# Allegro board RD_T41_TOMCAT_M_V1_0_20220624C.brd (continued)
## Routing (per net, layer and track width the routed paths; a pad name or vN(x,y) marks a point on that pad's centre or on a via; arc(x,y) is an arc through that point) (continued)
GMAC_TXD0: length 11.3
  TOP w0.102: U6.R11 27.47,22.53 27.02,22.53 26.82,22.33 20.21,22.33 19.35,21.46 19.35,19.81 19.22,19.68 U8.16
GMAC_TXD1: length 10.2
  TOP w0.102: U8.17 18.08,20.57 20.09,22.58 26.23,22.58 26.29,22.53 26.62,22.53 26.94,22.86 U6.T11
GMAC_TXEN: length 11.2
  TOP w0.102: U8.20 16.58,20.9 16.84,21.16 18.31,21.16 19.96,22.81 26.45,22.81 U6.U11
HPOUTL: length 7.6
  TOP w0.254: C107.2 20.61,30.25 26.25,30.25 U6.T1
I2C0_SCK: length 15.3
  TOP w0.102: U6.J4 32.03,27.74 32.03,34.42 v1(31.11,35.33)
  BOTTOM w0.102: v1(31.11,35.33) 30.81,35.03 25.73,35.03 25.25,34.55 J3.20
I2C0_SDA: length 13.4
  TOP w0.102: U6.J1 31.7,29.79 31.8,29.9 31.8,34.06 30.5,35.36 v1(30.5,35.48)
  BOTTOM w0.102: v1(30.5,35.48) 30.32,35.31 25.4,35.31 24.75,35.95 J3.19
IR: length 28.3
  TOP w0.102: v1(37.49,22.1) 37.11,22.1 37,22.21 U6.B12
  L3_PWR w0.102: v1(40.69,31.72) 40.56,31.85 34.16,31.85 v1(33.85,32.16)
  BOTTOM w0.102: J3.26 28.25,33.62 29.82,32.05 33.75,32.05 v1(33.85,32.16) ; v1(40.69,31.72) 40.84,31.72 41.4,31.17 41.4,23.01 40.41,22.02 37.56,22.02 v1(37.49,22.1)
IRCUTN: length 37.1
  TOP w0.102: U6.E17 35.06,18.19 37.13,18.19 38.55,19.61 v1(38.55,20.98)
  BOTTOM w0.102: J3.25 27.75,35.85 27.94,35.66 30.02,35.66 31.21,36.86 36.45,36.86 41.93,31.37 41.93,22.58 40.76,21.41 38.99,21.41 v1(38.55,20.98)
IRCUTP: length 36.6
  TOP w0.102: U6.E16 34.3,19.42 35.25,18.47 37.08,18.47 38.02,19.41 v1(38.02,21.54)
  BOTTOM w0.102: J3.24 27.25,34.59 27.45,34.8 30.53,34.8 31.37,33.96 35.23,33.96 35.81,34.54 38.43,34.54 41.65,31.32 41.65,22.76 40.59,21.69 38.17,21.69 v1(38.02,21.54)
LINKA: length 3.2
  TOP w0.102: R75.2 11.58,22.06 11.24,21.72 R76.1 10.47,20.47 J5.8
MCLK: length 1.1
  TOP w0.102: R67.2 34.3,29.8 U6.E1
MDI_RN: length 1.9
  TOP w0.104: R40.2 20.01,12.19 U9.1
MDI_RP: length 1.6
  TOP w0.104: U9.3 R39.2
MDI_TN: length 4.4
  TOP w0.104: U9.6 13.66,11.4 13.36,11.71 12.87,11.71 12.67,11.91 12.67,12.12 13.67,13.12 R36.2
MDI_TP: length 3.6
  TOP w0.104: R13.2 12.91,12.74 12.39,12.22 12.39,11.89 12.19,11.68 11.5,11.68 11.12,11.3 U9.8
MICBIAS: length 11.7
  TOP w0.254: U6.P3 v1(28.12,28.38) ; R81.1 20.61,33.07 C110.1 v1(21.54,32.78)
  BOTTOM w0.254: v1(28.12,28.38) 28.12,28.84 28.01,28.95 28.01,30.54 27.43,31.13 C79.1 C78.1 26.44,31.13 25.28,32.28 22.03,32.28 v1(21.54,32.78)
MICNL: length 12.1
  TOP w0.152: C68.2 23.4,31.62 20.62,31.62 20.23,32.02 17.7,32.02 R48.1 16.81,31.84 C105.1 16.3,32.02 14.08,32.02 13.29,32.81 J6.1
MICPL: length 10.7
  TOP w0.152: C67.2 23.43,31.98 20.77,31.98 20.37,32.37 17.7,32.37 R51.2 16.81,32.55 C105.2 16.3,32.37 14.93,32.37 14.54,32.76 J6.2
MIPI_RX_CLKN: length 23.9
  TOP w0.104: v1(15.62,34.99) 15.81,34.99 16.4,34.39 19.4,34.39 21.12,36.11 23.31,36.11 24.79,34.63 27.66,34.63 28,34.29 28,34.14 27.83,33.96 27.83,33.82 27.93,33.71 28.08,33.71 28.26,33.89 28.4,33.89 28.51,33.78 28.51,33.63 28.33,33.46 28.33,33.31 28.44,33.2 28.59,33.2 28.76,33.38 28.91,33.38 29.02,33.28 29.02,33.13 28.84,32.95 28.84,32.8 28.94,32.7 29.09,32.7 29.27,32.87 29.42,32.87 29.74,32.55 29.74,28.71 U6.M2
  BOTTOM w0.104: J3.2 16.25,34.55 15.81,34.99 v1(15.62,34.99)
MIPI_RX_CLKP: length 23.9
  TOP w0.104: v1(15.99,35.37) 15.99,35.17 16.51,34.65 19.29,34.65 21.02,36.37 23.41,36.37 24.9,34.89 27.77,34.89 30,32.66 30,29.74 29.95,29.69 29.95,29.16 30.07,29.03 30.07,28.38 U6.L3
  BOTTOM w0.104: J3.3 16.75,35.27 16.49,35.01 16.15,35.01 15.99,35.17 v1(15.99,35.37)
MIPI_RX_DN0: length 23.7
  TOP w0.102: 30.75,29.74 30.75,29.6 30.76,29.59 30.76,29.07 U6.L2
  TOP w0.104: 30.75,29.74 30.75,29.93 31.03,30.22 31.03,33.84 29.53,35.35 29.17,35.35 28.92,35.1 28.77,35.1 28.67,35.21 28.67,35.36 29.33,36.02 29.33,36.59 28.71,37.21 20.43,37.21 18.93,35.71 v1(18.73,35.71)
  BOTTOM w0.104: J3.5 17.75,35.97 18.31,35.41 18.62,35.41 18.73,35.52 v1(18.73,35.71)
MIPI_RX_DN1: length 23.8
  TOP w0.104: U6.N1 29.23,29.49 29.23,31.03 28.9,31.35 28.76,31.35 28.62,31.22 28.47,31.22 28.36,31.32 28.36,31.47 28.5,31.61 28.5,31.75 28.4,31.86 28.25,31.86 28.11,31.72 27.96,31.72 27.86,31.83 27.86,31.98 28,32.11 28,32.26 26.88,33.38 26.88,33.8 26.78,33.9 26.63,33.9 26.52,33.8 26.52,33.02 26.26,32.76 25.9,32.76 25.65,33.02 25.65,33.8 25.54,33.9 25.39,33.9 25.29,33.8 25.29,33.29 25.02,33.01 23.76,33.01 23.51,33.27 23.51,33.63 24.01,34.13 24.01,34.31 23.82,34.5 23.64,34.5 22.48,33.33 22.12,33.33 21.76,33.68 21.76,34.05 22.71,35 22.71,35.16 22.53,35.34 22.39,35.34 21.81,34.77 21.45,34.77 21.21,35.01 v1(21.02,35.01)
  BOTTOM w0.104: J3.8 19.25,34.6 19.99,35.33 20.89,35.33 21.02,35.2 v1(21.02,35.01)
MIPI_RX_DP0: length 23.7
  TOP w0.102: 30.4,29.74 U6.L1
  TOP w0.104: v1(19.11,35.34) 19.11,35.52 20.54,36.95 28.6,36.95 29.07,36.49 29.07,36.12 28.41,35.46 28.41,35.1 28.67,34.84 29.03,34.84 29.27,35.09 29.42,35.09 29.65,34.86 29.65,34.71 29.47,34.54 29.47,34.39 29.58,34.28 29.73,34.28 29.9,34.46 30.05,34.46 30.16,34.36 30.16,34.21 29.98,34.03 29.98,33.88 30.09,33.78 30.23,33.78 30.41,33.95 30.56,33.95 30.78,33.74 30.78,30.32 30.4,29.94 30.4,29.74
  BOTTOM w0.104: J3.6 18.25,35.04 18.35,35.15 18.72,35.15 18.91,35.34 v1(19.11,35.34)
MIPI_RX_DP1: length 23.8
  TOP w0.104: v1(21.39,35.39) 21.39,35.19 21.56,35.03 21.71,35.03 22.28,35.6 22.64,35.6 22.97,35.27 22.97,34.89 22.02,33.94 22.02,33.79 22.22,33.59 22.37,33.59 23.54,34.75 23.93,34.75 24.27,34.42 24.27,34.03 23.77,33.53 23.77,33.38 23.87,33.27 24.91,33.27 25.03,33.39 25.03,33.91 25.28,34.16 25.65,34.16 25.91,33.91 25.91,33.12 26.01,33.02 26.16,33.02 26.26,33.13 26.26,33.91 26.52,34.16 26.88,34.16 27.14,33.91 27.14,33.48 29.49,31.14 29.49,29.29 29.42,29.22 29.42,28.38 U6.M3
  BOTTOM w0.104: v1(21.39,35.39) 21.2,35.39 20.99,35.6 20.1,35.6 19.75,35.95 J3.9
MSC0_CLK_PB04: length 6.4
  TOP w0.102: J2.5 28.22,15.14 28.52,15.44 31.47,15.44 32.46,16.43 R25.1
MSC0_CMD_PB05: length 8.3
  TOP w0.102: v1(30.42,12.85) J2.3 30.42,15.08 30.55,15.21 31.67,15.21 33,16.54 U6.G17
  BOTTOM w0.102: v1(30.42,12.85) 30.43,12.86 R30.2
MSC0_D0_PB00: length 12.8
  TOP w0.102: v1(26.02,12.85) J2.7 26.02,15.08 26.72,15.77 31.36,15.77 31.92,16.34 31.92,18.36 32.33,18.77 32.33,19.59 U6.H16
  BOTTOM w0.102: R29.2 26.1,12.93 v1(26.02,12.85)
MSC0_D1_PB01: length 14
  TOP w0.102: v1(24.92,12.85) J2.8 24.92,14.61 26.36,16.05 31.31,16.05 31.7,16.43 31.7,18.47 32.03,18.8 32.03,19.93 U6.J15
  BOTTOM w0.102: R31.2 24.85,12.92 v1(24.92,12.85)
MSC0_D2_PB02: length 8.5
  TOP w0.102: v1(32.62,12.85) J2.1 32.62,15.4 33.52,16.31 33.52,19.28 33.32,19.48 33.32,19.93 U6.G15
  BOTTOM w0.102: v1(32.62,12.85) 32.61,12.86 R32.2
MSC0_D3_PB03: length 8.1
  TOP w0.102: U6.G16 33,19.48 33.32,19.15 33.32,18.75 33.27,18.69 33.27,16.4 31.52,14.65 J2.2 v1(31.52,12.86)
  BOTTOM w0.102: v1(31.52,12.86) 31.52,12.86 R33.2
PHY_LED0: length 22.2
  TOP w0.102: R74.1 12.8,19.98 12.8,20.37 13.15,20.73 13.15,23.24 13.79,23.88 15.02,23.88 15.15,24 22.46,24 23.55,25.1 25.12,25.1 v1(25.78,24.43) ; U6.R13 v1(27.48,21.24)
  L3_PWR w0.102: v1(25.78,24.43) 27.48,22.73 v1(27.48,21.24)
PHY_LED1: length 19.6
  TOP w0.102: R75.1 12.84,24.31 v1(13.74,24.31) ; U6.R15 v1(27.48,19.94)
  L3_PWR w0.102: v1(27.48,19.94) 27.05,19.94 26.26,20.73 26.26,21.41 22.7,24.97 17.47,24.97 16.81,24.31 v1(13.74,24.31)
PHY_RST_N: length 3.9
  TOP w0.102: U6.T13 26.8,21.21 26.31,21.21 26.13,21.39 24.6,21.39 C61.2 R99.1
PHYLED0: length 8.4
  TOP w0.102: v1(14.52,23.24) 14.37,23.09 14.37,22.04 R88.2 14.58,21.38 U8.24 ; R77.2 12.9,20.97 12.9,23.04 v1(12.75,23.19)
  BOTTOM w0.102: v1(14.52,23.24) 14.19,23.57 13.64,23.57 13.25,23.19 v1(12.75,23.19)
PHYLED1: length 5.2
  TOP w0.102: R89.2 v1(13.92,21.18) 13.92,20.78 13.31,20.17 13.31,19.81 13.44,19.68 U8.25 ; R76.2 12.28,21.75 v1(12.49,21.97)
  BOTTOM w0.102: v1(12.49,21.97) 13.13,21.97 v1(13.92,21.18)
PLL_AVDD: length 2.9
  TOP w0.254: U6.D3 v1(35.27,28.38)
  BOTTOM w0.254: v1(35.27,28.38) 35.27,28.98 C63.1 C30.1 35.26,30.73 FB3.1
POR_CTRL: length 2.7
  TOP w0.102: R20.2 R78.2 30.81,18.45 30.81,19.37 U6.K16
PPRST_: length 20
  TOP w0.102: v1(36.01,12.88) 36.01,14.12 36.62,14.73 37.6,14.73 R62.2 C111.1 40.19,15.86 41.09,16.76 SW2.2 ; v1(29.66,19.08) 29.87,19.08 U6.L16
  BOTTOM w0.102: v1(36.01,12.88) 35.99,12.9 33.68,12.9 33.14,13.44 33.14,17.32 31.39,19.08 v1(29.66,19.08)
RD_N: length 13
  TOP w0.102: U6.U17 26.88,18.57
  TOP w0.104: R73.1 21,13.63 21,14.13 20.88,14.24 20.69,14.24 19.96,13.51 19.81,13.51 19.73,13.59 19.73,13.74 20.6,14.61 21.79,14.61 23.17,15.98 24.91,15.98 26.89,17.96 26.89,18.56 26.88,18.57
RD_P: length 13.1
  TOP w0.102: U6.T17 27.15,18.57
  TOP w0.104: R72.1 18.79,12.22 19.53,12.95 20.04,12.95 20.44,12.55 20.8,12.55 21.26,13 21.26,14.16 21.44,14.35 21.9,14.35 23.27,15.72 25.02,15.72 27.15,17.85 27.15,18.57
RST_OUT: length 3.8
  TOP w0.102: U6.J16 31.21,19.12 v1(31.21,18.69)
  BOTTOM w0.102: TP8.1 32.25,17.78 31.34,18.69 v1(31.21,18.69)
RX+: length 22
  TOP w0.254: v1(8.15,14.58) 8.15,14.57 8.5,14.22 J5.3 ; v1(18.49,3.15) 18.49,2.69 18.23,2.44 17.73,2.44 17.47,2.18 U9.14
  L2_GND w0.254: v1(8.15,14.58) 8.15,9.73 15.01,2.87 18.21,2.87 v1(18.49,3.15)
RX-: length 24.6
  TOP w0.254: J5.4 8.5,15.47 8.15,15.11 v1(8.15,15.11) ; v1(19.02,3.15) 19.02,2.69 19.27,2.44 19.76,2.44 20.01,2.18 U9.16
  L2_GND w0.254: v1(8.15,15.11) 7.93,15.11 7.62,14.8 7.62,9.51 14.79,2.34 18.43,2.34 19.02,2.93 v1(19.02,3.15)
RX_DV: length 3.1
  TOP w0.102: R68.1 28.77,18.33 28.77,20.58 U6.P14
RXD3: length 6.2
  TOP w0.102: U6.R14 27.46,20.57 26.11,20.57 24.94,19.41 23.92,19.41 23.11,18.59 v1(23.11,18.49)
  BOTTOM w0.102: v1(23.11,18.49) 23.11,18.44 23.1,18.43 R65.1
RXDV: length 1.9
  TOP w0.102: v1(18.21,14.78) 18.08,14.91 U8.8
  BOTTOM w0.102: v1(18.21,14.78) 18.21,14.59 R87.2
SD0_CD_N: length 33.1
  TOP w0.102: J2.9 v1(23.82,12.47) 24.71,11.58 32.66,11.58 34.21,13.13 34.21,15.54 36.6,17.93 37.23,17.93 38.99,19.68 38.99,21.89 38.38,22.5 36.6,22.5 U6.B11
  BOTTOM w0.102: Q1.1 24.2,14.62 C92.2 R34.2 22.93,12.85 23.31,12.47 v1(23.82,12.47)
SFC_CS_N: length 25
  TOP w0.102: U6.T4 26.21,27.41 25.75,26.95 22.5,26.95 21.59,26.04 20.34,26.04 20.09,26.29 18.18,26.29 v1(18.06,26.16)
  BOTTOM w0.102: U7.1 10.31,29.64 13.64,29.64 14.12,30.12 16.3,30.12 17.7,28.73 17.7,26.52 v1(18.06,26.16)
  BOTTOM w0.203: U7.1 7.83,32.12 R22.1
SFC_SCLK: length 14.9
  TOP w0.102: U6.R6 27.47,25.78 23.24,25.78 22.25,24.79 17.14,24.79 v1(16.61,25.32)
  BOTTOM w0.102: v1(16.61,25.32) 16.61,26.93 U7.6
SFC_SIO0: length 13.1
  TOP w0.102: v1(17.27,26.16) 17.62,25.81 18.28,25.81 18.49,26.01 19,26.01 19.48,25.53 21.87,25.53 22.81,26.47 26.21,26.47 U6.U5
  BOTTOM w0.102: 16.57,28.77 17.27,28.07 v1(17.27,26.16)
SFC_SIO1: length 23
  TOP w0.102: v1(18.79,25.65) 19.17,25.27 21.99,25.27 22.96,26.24 26.56,26.24 26.77,26.44 27.48,26.44 U6.R5
  BOTTOM w0.102: U7.2 10.6,31.14 15.72,31.14 18.03,28.83 18.03,27.03 18.79,26.26 v1(18.79,25.65)
SFC_SIO2: length 21.3
  TOP w0.102: v1(19.63,25.93) 19.78,25.78 21.71,25.78 22.63,26.7 25.9,26.7 26.27,27.06 26.84,27.06 U6.T5
  BOTTOM w0.102: v1(19.63,25.93) 18.41,27.15 18.41,28.83 15.16,32.08 11.46,32.08 U7.3
SFC_SIO3: length 14.1
  TOP w0.102: v1(16.05,25.86) 16.68,25.86 17.5,25.04 22.12,25.04 23.08,26.01 27.05,26.01 U6.T6
  BOTTOM w0.102: U7.7 14.77,27.22 14.9,27.22 16.05,26.08 v1(16.05,25.86)
SPEAK_EN: length 42.7
  TOP w0.102: U6.B10 36.46,23.29 39.21,23.29 40.1,24.18 40.1,26.04 v1(40.86,26.8) ; R50.1 17.27,28.01 U10.1 14.63,28.01 v1(14.17,28.46)
  L3_PWR w0.102: v1(14.17,28.46) 17.32,28.46 19.23,30.38 35.02,30.38 35.86,31.22 40.1,31.22 41.13,30.19 41.13,27.06 v1(40.86,26.8)
TD_N: length 17.3
  TOP w0.104: v1(19,14.5) 19.24,14.5 19.98,15.25 21.59,15.25 22.96,16.62 24.06,16.62 25.84,18.4 25.84,19.11 26.33,19.61 U6.U16 ; v1(14.73,11.91) 14.83,12.01 R28.1
  BOTTOM w0.104: v1(14.73,11.91) 14.53,11.7 14.53,11.43 14.63,11.33 16.35,11.33 18.54,13.51 18.54,13.83 19,14.29 v1(19,14.5)
TD_P: length 18.5
  TOP w0.104: R13.1 v1(14.07,11.94) ; U6.T16 26.82,19.28 26.37,19.28 26.1,19.01 26.1,18.29 24.16,16.36 23.07,16.36 21.7,14.99 20.09,14.99 19.38,14.28 v1(19.38,14.13)
  BOTTOM w0.104: v1(19.38,14.13) 19.2,14.13 18.8,13.72 18.8,13.41 16.46,11.07 14.53,11.07 14.27,11.33 14.27,11.75 v1(14.07,11.94)
TRXN0: length 2
  TOP w0.104: U8.4 16.08,14.76 R36.1
TRXN1: length 3.7
  TOP w0.104: U8.6 17.08,14.98 16.96,14.87 16.96,14.5 17.27,14.2 18.01,14.2 R40.1
TRXP0: length 3.2
  TOP w0.104: U8.3 15.58,15.28 15.68,15.17 15.68,14.73 15.43,14.48 15.03,14.48 14.41,13.86 R35.1
TRXP1: length 3.8
  TOP w0.104: R39.1 17.89,13.25 18.11,13.46 18.11,13.73 17.9,13.94 17.16,13.94 16.7,14.4 16.7,14.86 16.58,14.98 U8.5
TX+: length 18.3
  TOP w0.254: U9.9 11.12,2.21 11.38,2.46 11.85,2.46 12.1,2.72 v1(12.1,3.11) ; v1(6.52,13) 7.84,13 8.23,12.62 8.23,12.1 8.61,11.72 J5.1
  L2_GND w0.254: v1(12.1,3.11) 12.1,3.5 6.52,9.08 v1(6.52,13)
TX-: length 18.6
  TOP w0.254: U9.11 13.66,2.21 13.41,2.46 12.92,2.46 12.67,2.72 v1(12.67,3.12) ; v1(6.52,13.54) 8.07,13.54 8.59,13.01 8.62,13.01 8.66,12.97 J5.2
  L2_GND w0.254: v1(6.52,13.54) 6.75,13.54 7.06,13.23 7.06,9.3 12.67,3.68 v1(12.67,3.12)
UART1_RX: length 43.3
  TOP w0.102: U6.F16 33.75,19.5 33.75,16.18 33.19,15.62 33.19,12.85 32.66,12.32 30.15,12.32 v1(30.02,12.19)
  L3_PWR w0.102: v1(30.02,12.19) 30.32,11.89 30.32,10.29 29.97,9.94 29.97,7.27 27.81,5.11 16.15,5.11 13.03,8.23 13.03,14.22 13.66,14.86 v1(14.04,14.86)
  BOTTOM w0.102: R61.2 14.04,14.75 v1(14.04,14.86)
UART1_RXD: length 2.9
  BOTTOM w0.102: R57.2 12.25,13.13 R61.1 11.5,14.75 J8.3
UART1_TX: length 44.6
  TOP w0.102: v1(30.83,11.96) 32.64,11.96 33.42,12.75 33.42,15.52 33.98,16.08 33.98,19.92 U6.F15
  L3_PWR w0.102: v1(13.86,15.39) 13.17,15.39 12.78,15 12.78,8.13 16.05,4.86 27.73,4.86 27.73,4.85 27.91,4.85 30.22,7.16 30.22,9.86 30.55,10.19 30.55,11.69 v1(30.83,11.96)
  BOTTOM w0.102: v1(13.86,15.39) 13.86,15.27 13.48,14.88 R60.2
UART1_TXD: length 2.6
  BOTTOM w0.102: R60.1 12.26,14.9 R58.2 12.25,15.75 J8.4
USB0PN: length 14.6
  TOP w0.13: v1(13.25,25.68) 13.32,25.6 13.94,25.6 15.54,27.2 20.7,27.2 21.1,27.61 R100.2
  BOTTOM w0.13: v1(13.25,25.68) 13.25,25.63 13.57,25.31 13.57,24.78 12.85,24.05 12.32,24.05 D5.2 11.99,23.74 11.67,24.05 10.72,24.05 10.55,23.89 J4.2
USB0PP: length 14.5
  TOP w0.13: R101.2 21.33,27.4 21.32,27.39 20.82,26.9 15.67,26.9 14.07,25.3 v1(12.87,25.3)
  BOTTOM w0.13: J4.3 10.55,24.54 10.73,24.36 11.69,24.36 D3.2 12.33,24.36 12.72,24.36 13.27,24.9 13.27,25.18 13.15,25.3 v1(12.87,25.3)
USB_AVD08: length 3.6
  TOP w0.254: U6.R4 v1(27.47,27.73)
  BOTTOM w0.254: FB4.2 24.36,27.72 C71.1 C72.1 27.46,27.72 v1(27.47,27.73)
USB_AVD18: length 6
  TOP w0.254: v1(26.82,28.38) 27.15,28.06 U6.T3
  BOTTOM w0.254: FB5.2 21.69,27.72 C36.1 C73.1 23.44,27.86 23.96,28.38 v1(26.82,28.38)
USB_AVD33: length 5.5
  TOP w0.203: U6.R3 v1(27.47,28.38)
  BOTTOM w0.254: v1(27.47,28.38) 27,28.85 24.57,28.85 C75.1 C74.1 22.86,28.97 FB6.2
USBID: length 3.1
  TOP w0.102: U6.U2 26.24,28.45 24.56,28.45 TP7.1
N16515966: length 3.1
  BOTTOM w0.305: U2.3 33.17,9.74 R8.2 R6.2 C10.2
N16516036: length 1.2
  BOTTOM w0.254: R4.2 37.17,9.75 U2.4
N16516040: length 2.2
  BOTTOM w0.305: U2.1 35.19,7.84 35.87,7.15 C6.1
N16516370: length 4.9
  BOTTOM w0.203: U1.1 20.2,7.05 20.61,6.64 C3.1 R1.2
N16516568: length 2.9
  BOTTOM w0.305: C4.2 R2.1 R3.2 20.18,4.98 U1.5
N16516732: length 0.9
  BOTTOM w0.254: R14.1 D2.2
N16516898: length 5
  BOTTOM w0.254: R5.2 C14.1 39.28,15.86 39.01,15.6 36.95,15.6 36.49,16.06 U3.1
N16517024: length 2.9
  BOTTOM w0.305: C9.2 R7.1 R9.2 36.44,13.97 U3.5
N16520392: length 6.3
  TOP w0.406: v1(10.54,23.24) 10.54,23.24 D6.2
  BOTTOM w0.406: R85.1 C95.1 11.9,19.98 C119.1 11.9,21.88 v1(10.54,23.24) J4.1
N16524050: length 1.9
  TOP w0.254: U10.5 9.61,29.96 J7.2
N16524058: length 2
  TOP w0.254: U10.8 10.37,28.01 9.89,28.48 J7.1
N16524110: length 1.6
  TOP w0.254: U10.4 16.72,29.96 16.89,29.79 R53.1
N16524120: length 0.7
  TOP w0.254: R53.2 C107.1
N16524124: length 0.7
  TOP w0.254: R52.2 C106.1
N16524196: length 1.7
  TOP w0.254: R52.1 16.99,28.93 16.61,29.31 U10.3
N16524342: length 2.4
  TOP w0.254: R51.1 17.69,33.59 v1(18.36,32.92) 18.86,32.92 R81.2
  BOTTOM w0.254: C56.2 v1(18.36,32.92)
N16524476: length 2
  TOP w0.254: R48.2 18.35,30.8 v1(18.36,30.81) 18.65,30.81 R49.2
  BOTTOM w0.254: C56.1 v1(18.36,30.81)
N16557488: length 4.7
  TOP w0.102: C82.2 34.92,33.91 Y1.3 36.15,33.56 R24.1
N16609473: length 1.1
  TOP w0.254: v1(33.96,20.93) 33.96,21.24 U6.F13
  BOTTOM w0.254: R16.1 v1(33.96,20.93)
N16609477: length 3
  TOP w0.102: U6.D9 35.28,23.83 37.3,23.83 37.38,23.9 R18.1
N16629326: length 1.8
  TOP w0.102: R46.2 12.87,18.57 13.26,18.18 U8.28
N16629374: length 2.5
  TOP w0.102: R47.2 12.54,14.91 12.72,15.09 12.72,15.62 13.28,16.18 U8.32
N16629796: length 3.3
  TOP w0.102: R41.1 13.03,14.05 13.38,14.4 14.22,14.4 14.58,14.76 U8.1
N16629982: length 2.6
  TOP w0.254: C103.1 C104.1 12.3,17.68 U8.29
N16630018: length 2.5
  TOP w0.254: U8.2 v1(15.08,14.94)
  BOTTOM w0.254: C101.1 15.58,13.26 C102.1 15.58,14.44 v1(15.08,14.94)
N16630046: length 2.7
  TOP w0.102: R94.1 12.52,15.77 12.82,16.08 12.82,16.92 13.09,17.18 U8.30
N16630124: length 1.1
  TOP w0.406: U9.7 v1(12.17,10.59)
  BOTTOM w0.406: C98.2 11.26,10.59 v1(12.17,10.59)
N16630144: length 1.2
  TOP w0.508: U9.15 18.34,1.39 v1(18.33,1.4) ; v1(11.98,1.4) 11.99,1.39 U9.10 ; v1(15.77,1.4) 15.77,1.39 U9.13
N16630182: length 1.7
  TOP w0.406: v1(14.93,9.53) U9.5
  BOTTOM w0.406: C97.2 v1(14.93,9.53)
N16630194: length 3.7
  TOP w0.406: U9.2 18.74,9.68 17.85,8.79 v1(16.96,8.79)
  BOTTOM w0.406: v1(16.96,8.79) 16.84,8.79 16.82,8.8 C96.2
N16630328: length 3.5
  BOTTOM w0.508: R93.1 8.84,5.1 C126.2
N16642093: length 5.1
  BOTTOM w0.203: R10.2 19.39,18.3 18.98,18.71 C112.1 18.98,21.29 19.68,21.98 U5.1
N16679971: length 3
  TOP w0.102: R21.2 37.68,27.74 35.28,27.74 U6.D4
N16680187: length 8
  TOP w0.254: v1(25.45,31.01) 26.14,31.01 U6.R1
  BOTTOM w0.254: FB7.2 21.66,31.44 C66.1 22.65,31.43 C65.1 25.05,31.41 v1(25.45,31.01)
N16680357: length 2.5
  TOP w0.254: U6.R2 v1(27.47,29.03)
  BOTTOM w0.254: v1(27.47,29.03) 27.14,29.36 C70.1 C69.1
N16685513: length 2.9
  TOP w0.102: R66.2 26.71,23.72 U6.T9
N16707574: length 5.4
  TOP w0.13: U6.T2 26.82,29.03 22.96,29.03 22.42,28.49 R101.1
N16707578: length 4.9
  TOP w0.13: U6.U1 26.48,29.34 22.83,29.34 22.19,28.7 R100.1
N16707590: length 5.5
  TOP w0.102: U6.P2 28.45,28.85 28.11,29.18 28.11,29.64 28.04,29.72 28.04,29.74
  TOP w0.152: 28.04,29.74 28.04,29.95 26.37,31.61 24.94,31.61 C68.1
N16707598: length 0.4
  TOP w0.102: U6.P15 v1(28.13,19.94)
N16710875: length 2.4
  TOP w0.102: U6.H15 32.66,19.94 32.66,18.64 32.46,18.44 R25.2
N16712105: length 7
  TOP w0.102: 28.39,29.74 28.39,29.72 28.32,29.64 28.32,29.27 28.77,28.81 28.77,28.38 U6.N3
  TOP w0.152: 28.39,29.74 28.39,30.09 26.52,31.97 24.94,31.97 C67.1
N16792128: length 2.7
  TOP w0.102: R26.1 25.36,19.11 26.18,19.93 26.82,19.93 U6.T15
N16932770: length 4.9
  BOTTOM w0.203: R11.2 C62.1 26.91,6.64 26.55,7 U4.1
N16932830: length 2.9
  BOTTOM w0.305: U4.5 26.53,4.98 R98.2 R86.1 C16.2
N16990134: length 3.6
  TOP w0.102: R19.2 19.71,20.94 19.71,19.61 19.28,19.18 U8.15

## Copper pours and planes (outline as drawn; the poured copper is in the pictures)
GND on TOP: 35.91,19.76 36.6,20.45 36.6,27.91 35.81,28.7 28.32,28.7 27.17,27.56 27.17,20.32 27.73,19.76
GND on TOP: 6,0.41 5.58,0.58 5.41,1 5.41,37 5.58,37.42 6,37.59 42,37.59 42.42,37.42 42.59,37 42.59,1 42.42,0.58 42,0.41 ; 8 cut-outs
GND on BOTTOM: 6,0.41 5.58,0.58 5.41,1 5.41,37 5.58,37.42 6,37.59 42,37.59 42.42,37.42 42.59,37 42.59,1 42.42,0.58 42,0.41 ; 2 cut-outs
GND on L2_GND: 6,0.41 5.58,0.58 5.41,1 5.41,37 5.58,37.42 6,37.59 42,37.59 42.42,37.42 42.59,37 42.59,1 42.42,0.58 42,0.41
GND on L3_PWR: 6,0.41 5.58,0.58 5.41,1 5.41,37 5.58,37.42 6,37.59 42,37.59 42.42,37.42 42.59,37 42.59,1 42.42,0.58 42,0.41
VCC_0V8 on TOP: 31.44,20.98 32.18,20.98 32.81,21.62 32.81,27.23 32.71,27.33 29.49,27.33 28.09,25.93 28.09,23.7 28.49,23.29 29.16,23.29 29.31,23.44 29.31,24.1 29.28,24.13 29.28,25.43 30.27,26.42 31.82,26.42 32,26.24 32,22.23 31.72,21.95 30.96,21.95 30.45,21.44 29.89,21.44 29.59,21.13 29.59,20.7 29.71,20.57 31.03,20.57
VCC_0V8 on BOTTOM: 31.62,21.77 31.97,22.12 31.97,26.72 31.82,26.87 30.35,26.87 30.17,26.7 30.17,26.42 29.37,25.62 29.37,23.03 29.18,22.83 28.55,22.83 28.47,22.91 28.47,24.05 27.73,24.79 24.28,24.79 24.13,24.64 24.1,24.47 24.1,22.17 24.05,22.12 22.07,22.12 22.04,22.15 22.04,25.35 23.01,26.31 26.95,26.31 27.3,26.67 28.85,26.67 29.1,26.92 29.1,27.3 29.31,27.51 29.31,27.87 29.47,28.02 32.46,28.02 32.89,27.59 32.89,21.16 32.37,20.64 31.73,20.64 31.57,20.47 29.16,20.47 29.13,20.5 29.13,21.21 29.38,21.46 30.65,21.46 30.96,21.77
VCC_1V8 on BOTTOM: 27.17,11.33 27.07,11.43 24.99,11.43 24.68,11.13 24.68,9.58 24.81,9.45 27.12,9.45 27.17,9.5
VCC_1V8 on L3_PWR: 24.71,9.83 26.06,9.83 26.37,10.15 26.37,11.37 29.43,14.43 30.67,15.66 30.67,16.53 30.51,16.69 29.43,16.69 24.53,11.79 24.53,10.01
VCC_3V3 on BOTTOM: 17.95,9.45 17.89,9.51 17.89,11.11 18.28,11.51 18.28,11.96 20.34,14.02 20.34,16.76 20.52,16.94 21.59,16.94 21.66,16.87 21.66,13.84 19.63,11.81 19.63,11.43 19.73,11.33 20.77,11.33 20.82,11.28 20.82,9.55 20.72,9.45
VCC_3V3 on L3_PWR: 26.95,16.05 27.86,16.05 28.93,17.12 32.18,17.12 38.65,23.6 38.65,25.45 40.79,27.58 40.79,30.05 40.69,30.15 39.8,30.15 39.67,30.02 39.67,27.99 37.61,25.93 37.61,24.03 31.67,18.08 27.96,18.08 26.82,16.94 26.82,16.18
VCC_5V on BOTTOM: 21.54,5.66 21.66,5.79 22.53,5.79 22.83,5.49 22.83,5.18 22.93,5.08 23.52,5.08 23.54,5.05 23.54,2.59 23.69,2.44 27.56,2.44 27.89,2.77 27.89,5.71 27.96,5.79 28.93,5.79 29.23,5.49 29.23,5.21 29.33,5.11 30.02,5.11 30.15,5.23 30.15,10.62 32.04,12.51 37.14,12.51 37.69,13.06 37.69,14.68 37.82,14.81 38.81,14.81 39.32,14.3 39.85,14.3 40.1,14.05 40.1,12.6 38.91,11.4 32.58,11.4 31.21,10.03 31.21,5.38 31.38,5.22 31.78,5.22 32.41,5.84 34.36,5.84 34.51,5.99 35.56,5.99 35.58,5.97 35.58,3.99 35.53,3.94 34.13,3.94 34.03,4.04 33.07,4.04 32.66,3.63 32.66,1.98 31.7,1.02 21.79,1.02 21.54,1.27
VCC_5V on BOTTOM: 8.76,17.45 7.97,18.24 6.35,18.24 6.07,18.52 6.07,19.58 6.47,19.99 8.63,19.99 9.39,19.23 13.53,19.23 13.76,19.46 13.76,20.35 14.3,20.88 17.85,20.88 18.03,20.7 18.03,19.76 17.95,19.68 16.07,19.68 15.77,19.38 15.77,17.7 15.52,17.45
VCC_5V on L3_PWR: 6.37,19.94 8.71,19.94 8.95,19.7 8.95,10.78 16.02,3.71 23.26,3.71 23.75,3.23 23.75,1.37 23.36,0.99 13.23,0.99 6.07,8.15 6.07,19.63
VCC_12V on TOP: 38.07,8.41 42.16,8.41 42.41,8.15 42.41,6.73 42.24,6.55 38.45,6.55 38.05,6.96 38.05,8.38
VCC_12V on BOTTOM: 38.2,8.36 38.68,7.87 38.68,7.24 39.34,6.58 42.19,6.58 42.41,6.81 42.41,9.32 42.29,9.45 37.97,9.45 37.74,9.22 36.7,9.22 36.65,9.17 36.65,8.41 36.7,8.36
VCC_DDR on TOP: 33.52,27.08 33.52,22 33.88,21.64 34.74,21.64 34.87,21.77 34.87,25.88 34.08,26.67 34.08,26.87 34.18,26.97 34.18,27.25 34.11,27.33 33.78,27.33
VCC_DDR on BOTTOM: 34.72,18.36 34.36,18.72 34.36,21.34 34.11,21.59 33.91,21.59 33.78,21.72 33.78,27.28 33.83,27.33 34.24,27.33 34.29,27.28 34.29,26.92 34.46,26.75 35.28,26.75 35.58,26.44 35.58,22.78 35.96,22.4 35.96,21.54 36.09,21.41 36.09,20.57 36.24,20.42 37,20.42 37.16,20.27 37.16,18.52 37,18.36
N16516056 on BOTTOM: 36.65,8.03 36.65,6.4 36.92,6.13 36.92,3.95 37.03,3.84 38.48,3.84 38.73,4.09 38.73,6.53 38.22,7.04 38.22,7.72 37.89,8.05 36.67,8.05
N16516600 on BOTTOM: 21.81,7.24 22.7,7.24 22.81,7.34 22.81,8.46 23.31,8.97 23.31,11.18 23.06,11.43 21.81,11.43 21.74,11.35 21.74,8.94 21.79,8.89 21.79,7.26
N16517036 on BOTTOM: 38.1,16.26 38.93,16.26 39.09,16.41 39.09,17.45 39.67,18.03 39.67,20.14 39.42,20.4 38.15,20.4 38.07,20.32 38.07,16.28
N16630144 on BOTTOM: 10.33,2.06 13.28,2.06 13.53,2.31 13.53,2.95 15.49,4.9 15.64,4.9 17.22,3.33 17.22,2.44 17.75,1.91 18.49,1.91 18.89,1.5 18.89,1.17 18.74,1.02 10.41,1.02 10.18,1.24 10.18,1.91
N16642355 on BOTTOM: 19.48,20.37 19.48,19.66 19.71,19.43 23.9,19.43 24.1,19.63 24.1,20.65 24.05,20.7 21.41,20.7 21.13,20.42 19.53,20.42
N16932828 on BOTTOM: 28.14,7.26 28.16,7.24 29.05,7.24 29.16,7.34 29.16,8.41 29.59,8.84 29.59,11.3 29.46,11.43 28.16,11.43 28.09,11.35 28.09,8.86 28.14,8.81

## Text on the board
BOTTOM: ArtWork BOTTOM
Package Geometry/Pastemask Bottom: ArtWork Pastebot
Ref Des/Silkscreen Bottom: ADC0 | RST_OUT | USB | DEBUG | 3V3 | 0V8 | 1V8 | 5V | VCCDDR | MIPI_CON | 12V | ArtWork Silkbot
User.Comments: ArtWork Soldertop | ArtWork Solderbot
TOP: ArtWork TOP
Package Geometry/Pastemask Top: ArtWork Pastetop
Ref Des/Silkscreen Top: ETH | R- | R+ | T- | T+ | SPK | MIC | USBID | SDCARD | VBUS | BOOTSEL0 | GND | 12V | NC | PPRST_ | ArtWork Silktop
L2_GND: ArtWork L2_GND
L3_PWR: ArtWork L3_PWR
DIMENSION: 1,4 | 4X
NCLEGEND-1-4: FIGURE | SIZE | 8.0 | 23.622 | 39.37 | 47.244x19.685 | 118.11x78.74 | DRILL CHART: TOP to BOTTOM | ALL UNITS ARE IN MILS | PLATED | NON-PLATED | QTY | 501 | 2
